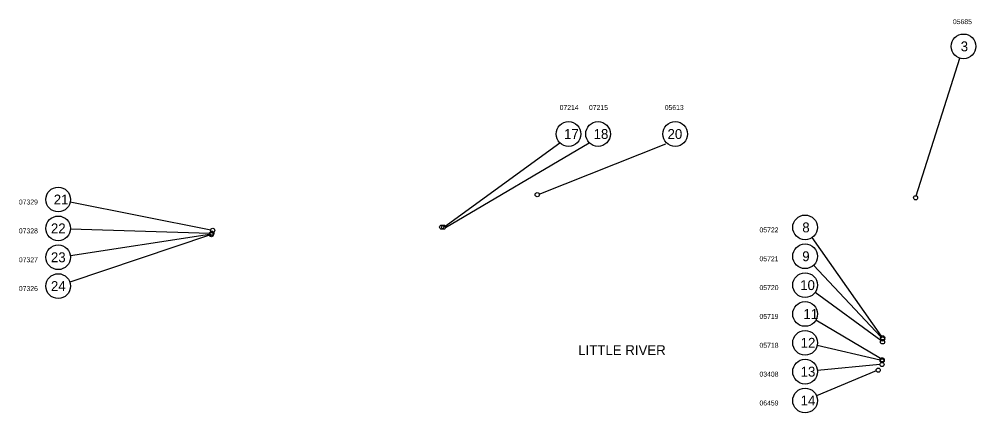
# Model space of a CAD drawing. Extents: x -43543 to 34500, y -13675 to 11152.
# Drawn here: x -43543 to -20334, y -1897 to 7656 of the extents above; entities that cross this region are included whole.
import ezdxf

# ---------------------------------------------------------------- set-up
doc = ezdxf.new("R2010")
doc.units = 0
for name, color, linetype in [('2', 7, 'Continuous'), ('R_Annotation', 7, 'Continuous'), ('R_No Plot', 7, 'Continuous')]:
    doc.layers.add(name, color=color, linetype=linetype)

msp = doc.modelspace()

# ---------------------------------------------------------------- linework, layer by layer
at = {"layer": 'R_Annotation'}
for p, q in [((-21781, 3369), (-20725, 6709)), ((-33243, 2610), (-30429, 4657)), ((-33197, 2600), (-29712, 4657)), ((-30928, 3413), (-27857, 4628)), ((-42302, 3221), (-38896, 2542)), ((-42296, 2570), (-38918, 2466)), ((-38927, 2413), (-42312, 1275)), ((-42299, 1925), (-38923, 2441)), ((-22623, -33), (-24305, 2358)), ((-22640, -51), (-24272, 1685)), ((-22636, -142), (-24235, 1026)), ((-22648, -580), (-24219, 351)), ((-22655, -617), (-24185, -264)), ((-22751, -874), (-24201, -1481)), ((-22660, -722), (-24179, -868))]:
    msp.add_line(p, q, dxfattribs=at)
for centre, radius in [((-20634, 6995), 300), ((-30216, 4869), 300), ((-29499, 4869), 300), ((-27628, 4869), 300), ((-42596, 3279), 300), ((-30975, 3398), 50), ((-21797, 3322), 50), ((-42596, 2579), 300), ((-24477, 2603), 300), ((-38847, 2532), 50), ((-33293, 2610), 50), ((-33246, 2609), 50), ((-38880, 2428), 50), ((-38873, 2449), 50), ((-38868, 2464), 50), ((-42596, 1879), 300), ((-24477, 1903), 300), ((-42596, 1179), 300), ((-24477, 1203), 300), ((-24477, 503), 300), ((-24477, -197), 300), ((-22598, -175), 50), ((-22596, -75), 50), ((-22596, -104), 50), ((-24477, -897), 300), ((-22610, -724), 50), ((-22608, -609), 50), ((-22608, -634), 50), ((-22703, -860), 50), ((-24477, -1597), 300)]:
    msp.add_circle(centre, radius, dxfattribs=at)

# ---------------------------------------------------------------- texts
at = {"layer": '2'}
msp.add_text('LITTLE RIVER', height=240, dxfattribs=at).set_placement((-29980, -494))
at = {"layer": 'R_Annotation'}
for s, p in [('3', (-20702, 6875)), ('17', (-30324, 4749)), ('18', (-29607, 4749)), ('20', (-27814, 4749)), ('21', (-42704, 3159)), ('22', (-42772, 2459)), ('8', (-24545, 2483)), ('23', (-42772, 1759)), ('9', (-24546, 1783)), ('24', (-42772, 1059)), ('10', (-24596, 1083)), ('11', (-24517, 383)), ('12', (-24585, -317)), ('13', (-24585, -1017)), ('14', (-24585, -1717))]:
    msp.add_text(s, height=240, dxfattribs=at).set_placement(p)
at = {"layer": 'R_No Plot'}
for s, p in [('05685', (-20891, 7535)), ('07214', (-30431, 5452)), ('07215', (-29720, 5452)), ('05613', (-27882, 5452)), ('07329', (-43549, 3159)), ('07328', (-43549, 2459)), ('05722', (-25583, 2483)), ('07327', (-43549, 1759)), ('05721', (-25583, 1783)), ('07326', (-43549, 1059)), ('05720', (-25583, 1083)), ('05719', (-25583, 383)), ('05718', (-25583, -317)), ('03408', (-25583, -1017)), ('06459', (-25583, -1717))]:
    msp.add_text(s, height=120, dxfattribs=at).set_placement(p)

doc.saveas('drawing.dxf')
